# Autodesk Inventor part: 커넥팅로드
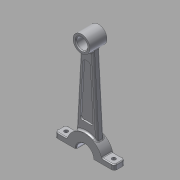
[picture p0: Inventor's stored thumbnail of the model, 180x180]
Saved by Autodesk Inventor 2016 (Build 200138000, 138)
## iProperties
Created: 2016-11
Part Number: 커넥팅로드
Material: 알루미늄 6061
Document SubType Name: Modeling
Designer: mduedu
Density: 2.71 g/cm^3
Mass: 62.0571 g
Surface Area: 108.143 cm^2
Volume: 22.8993 cm^3
Appearance: 알루미늄 - 평지
Author: mduedu
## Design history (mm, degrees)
sketch "스케치1" dims "d0" = 42, "d3" = 20
  geometry: L1 (0, 0)-(0, 114); L2 (-7.5, 107.386)-(-12.5, 16.875); L3 (7.5, 107.386)-(12.5, 16.875); C1 r 10 at (0, 0); C2 r 6.5 at (0, 114); 3 further points
  constraints: 6 end point, 4 coincident, 2 centre point, 2 symmetric about line, 1 vertical, 6 other
  dimensions: "d1" = 20 diameter of C1; "d2" = 13 diameter of C2; "d4" = 114 distance of L1.start L1.end; "d6" = 12.5 distance from line of L1 L2.end; "d7" = 7.5 distance from line of L1 L2.start
extrude "돌출1" new body sketch "스케치1" stored distance "d8" = 13; taper "d9" = 0 deg
extrude "돌출2" join sketch "스케치1" stored distance "d10" = 20; taper "d11" = 0 deg
sketch "스케치2"
  geometry: L1 (-7.5, 107.386)-(-12.5, 16.875) reference; L2 (7.5, 107.386)-(12.5, 16.875) reference; A1 r 10 centre (0, 114) between (-7.5, 107.386) and (7.5, 107.386) reference; A2 r 21 centre (0, 0) between (-12.5, 16.875) and (12.5, 16.875) reference; 1 further point
extrude "돌출3" join sketch "스케치2" stored distance "d12" = 8; taper "d13" = 0 deg
sketch "스케치3"
  geometry: L1 (-7.5, 107.386)-(-12.5, 16.875) reference; L2 (7.5, 107.386)-(12.5, 16.875) reference; L3 (-4.209, 94.448)-(-7.768, 30.011); L4 (4.209, 94.448)-(7.768, 30.011); L5 (0, 94)-(0, 31); A1 r 10 centre (0, 114) between (-7.5, 107.386) and (7.5, 107.386) reference; A2 r 21 centre (0, 0) between (-12.5, 16.875) and (12.5, 16.875) reference; A3 r 20 centre (0, 114) between (-4.209, 94.448) and (4.209, 94.448); A4 r 31 centre (0, 0) between (7.768, 30.011) and (-7.768, 30.011); 1 further point
  constraints: 6 end point, 6 point on circle, 2 centre point, 2 parallel, 1 symmetric about line, 1 vertical alignment
  dimensions: "d18" = 10 radial gap between concentric circles of A3 A1; "d19" = 10 radial gap between concentric circles of A2 A4; "d20" = 4 distance between parallel lines of L3 L1
extrude "돌출4" cut sketch "스케치3" distance "d21" = 2; taper "d22" = 0 deg
fillet "모깎기1" dims "d23" = 3
fillet "모깎기2" dims "d24" = 2
fillet "모깎기3" dims "d25" = 2
chamfer "모따기1" distance "d26" = 1; stored, may be unused: second distance "d27" = 2, angle "d28" = 45 deg
sketch "스케치4"
  geometry: L1 (-35, -6)-(-20.125, -6); L2 (35, -6)-(35, 6); L3 (35, 6)-(20.125, 6); L4 (-35, 6)-(-35, -6); L5 (-35, -6)-(35, 6); L6 (35, -6)-(-35, 6); L7 (-20.125, 6)-(-35, 6); L8 (20.125, 6)-(-20.125, 6); L9 (20.125, -6)-(35, -6); L10 (-20.125, -6)-(20.125, -6); A1 r 21 centre (0, 0) between (-20.125, 6) and (20.125, 6) reference; 1 further point
  constraints: 20 end point, 10 parallel, 4 point on circle, 3 horizontal, 3 perpendicular, 2 midpoint
  dimensions: "d29" = 70 distance of L1.start L2.start; "d31" = 12 distance of L2.start L2.end
extrude "돌출5" join sketch "스케치4" stored distance "d32" = 0; taper "d33" = 0 deg
fillet "모깎기4" dims "d34" = 3
fillet "모깎기5" dims "d35" = 1
fillet "모깎기6" dims "d36" = 1
sketch "스케치5"
  geometry: L1 (1, 0)-(1, 7) reference; L2 (-24, 13.5)-(-44, 13.5) reference; L3 (-44, -6.5)-(-24, -6.5) reference; L4 (-34, 13.5)-(-34, -6.5); 3 further points
  constraints: 2 end point, 2 midpoint, 1 horizontal alignment, 1 symmetric about line
  dimensions: "d37" = 7 distance from line of point (-6, 3.5) L1
feature "분할1"
sketch "스케치6"
  geometry: 2 further points
  constraints: 2 other
hole "구멍1" sketch "스케치6" at (-62, 3.5), (-6, 3.5) diameter "d38" = 4.5; stored, may be unused: countersink angle "d42" = 90 deg, drill point angle "d44" = 0 deg; dims "d39" = 6, "d40" = 4, "d41" = 2, "d43" = 8
node "솔리드1"
mirror "대칭1"
other parameters: "d16" = 4, "d17" = 4
